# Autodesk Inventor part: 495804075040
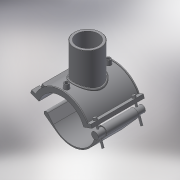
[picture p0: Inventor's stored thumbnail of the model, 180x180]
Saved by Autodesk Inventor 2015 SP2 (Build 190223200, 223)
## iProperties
Created: 2017-07
Part Number: 495804075040
Material: Generic
Description: PLASSON BRANCH SADDLE 75-40
Document SubType Name: Modeling
Designer: KIM
Density: 1 g/cm^3
Appearance: Default
Author: KIM
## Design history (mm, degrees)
derived "495804.ipt"
feature "Solid1::495804.ipt"
feature "Solid2::495804.ipt"
tag "TaggingFeature1"
body "Solid1"
body "Solid2"
other parameters: "d0" = 75, "d2" = 117, "d3" = 18.75, "d4" = 118, "d5" = 0, "d6" = 0.1, "d8" = 0, "d19" = 6, "d20" = 6, "d21" = 70.8, "d23" = 0, "d24" = 35.4, "d26" = 0, "d27" = 3, "d28" = 3, "d29" = 3, "d30" = 25, "d31" = 6, "d32" = 0, "d33" = 0, "d34" = 0.6, "d40" = 51.48, "d41" = 44, "d43" = 0, "d45" = 0, "d47" = 127.5, "d50" = 0, "d70" = 15, "d72" = 0, "d73" = 6, "d75" = 5, "d76" = 0, "d77" = 3.75, "d78" = 67.5, "d79" = 15, "d80" = 47.2, "d82" = 5 deg, "d84" = 4, "d85" = 14, "d86" = 0, "d87" = 3, "d88" = 0, "d89" = 1, "d90" = 1, "d91" = 94.4, "d92" = 0, "d93" = 0.5, "d94" = 39.47368, "d96" = 100.98, "d97" = 2.36, "d98" = 0, "d102" = 1.2, "d103" = 32, "d105" = 0, "d109" = -26, "d117" = 0.4, "d120" = 140 deg, "d121" = 24.228, "d122" = 20 deg, "d123" = 198, "d124" = 59.4, "d126" = 0, "d143" = 78.75, "d150" = 13.5, "d159" = 4.8, "d161" = 1.875, "d162" = 70.8, "d163" = 0, "d167" = 15, "d168" = 45, "d173" = 1, "d175" = 37.5, "d176" = 20 deg, "d177" = 5.25, "d178" = 24, "d180" = 0, "d185" = 38.35, "d186" = 38.35, "d187" = 49.5, "d188" = 7.2, "d189" = 5.25, "d190" = 0, "d191" = 74.25, "d200" = 12, "d202" = 0, "d216" = 106.2, "d217" = 0, "d221" = 43.66, "d222" = 5.25, "d223" = 3.15, "d224" = 37.5, "d225" = 3.15, "d227" = 10.8, "d230" = 46.5, "d236" = 20 deg, "d237" = 56.5, "d238" = 20 deg, "d239" = 5.25, "d_" = 75, "B_" = 117, "H_" = 78, "L_" = 118, "d_t" = 6, "H_1" = 66, "d1" = 99, "d148" = 1.875, "d160" = 1.875
